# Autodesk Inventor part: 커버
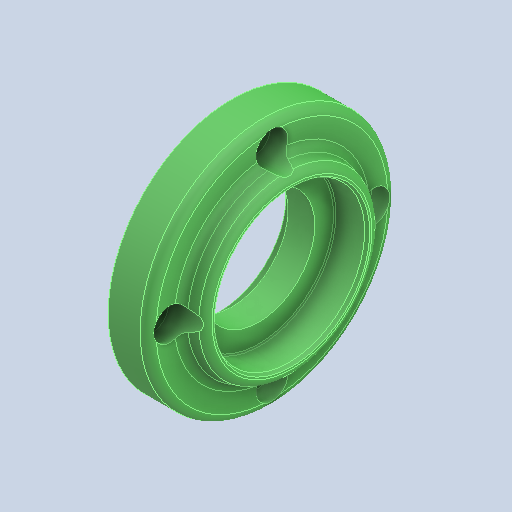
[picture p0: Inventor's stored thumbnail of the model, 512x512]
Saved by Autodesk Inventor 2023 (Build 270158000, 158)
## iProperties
Created: 2025-03
Part Number: 커버
Material: 알루미늄 6061
Document SubType Name: Modeling
Designer: User
Density: 2.71 g/cm^3
Appearance: 기본값
Author: jhkim
Sending System: Autodesk Inventor 2025
Preprocessor: ST-DEVELOPER v20
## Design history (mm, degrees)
feature "솔리드1"
node "솔리드2"
